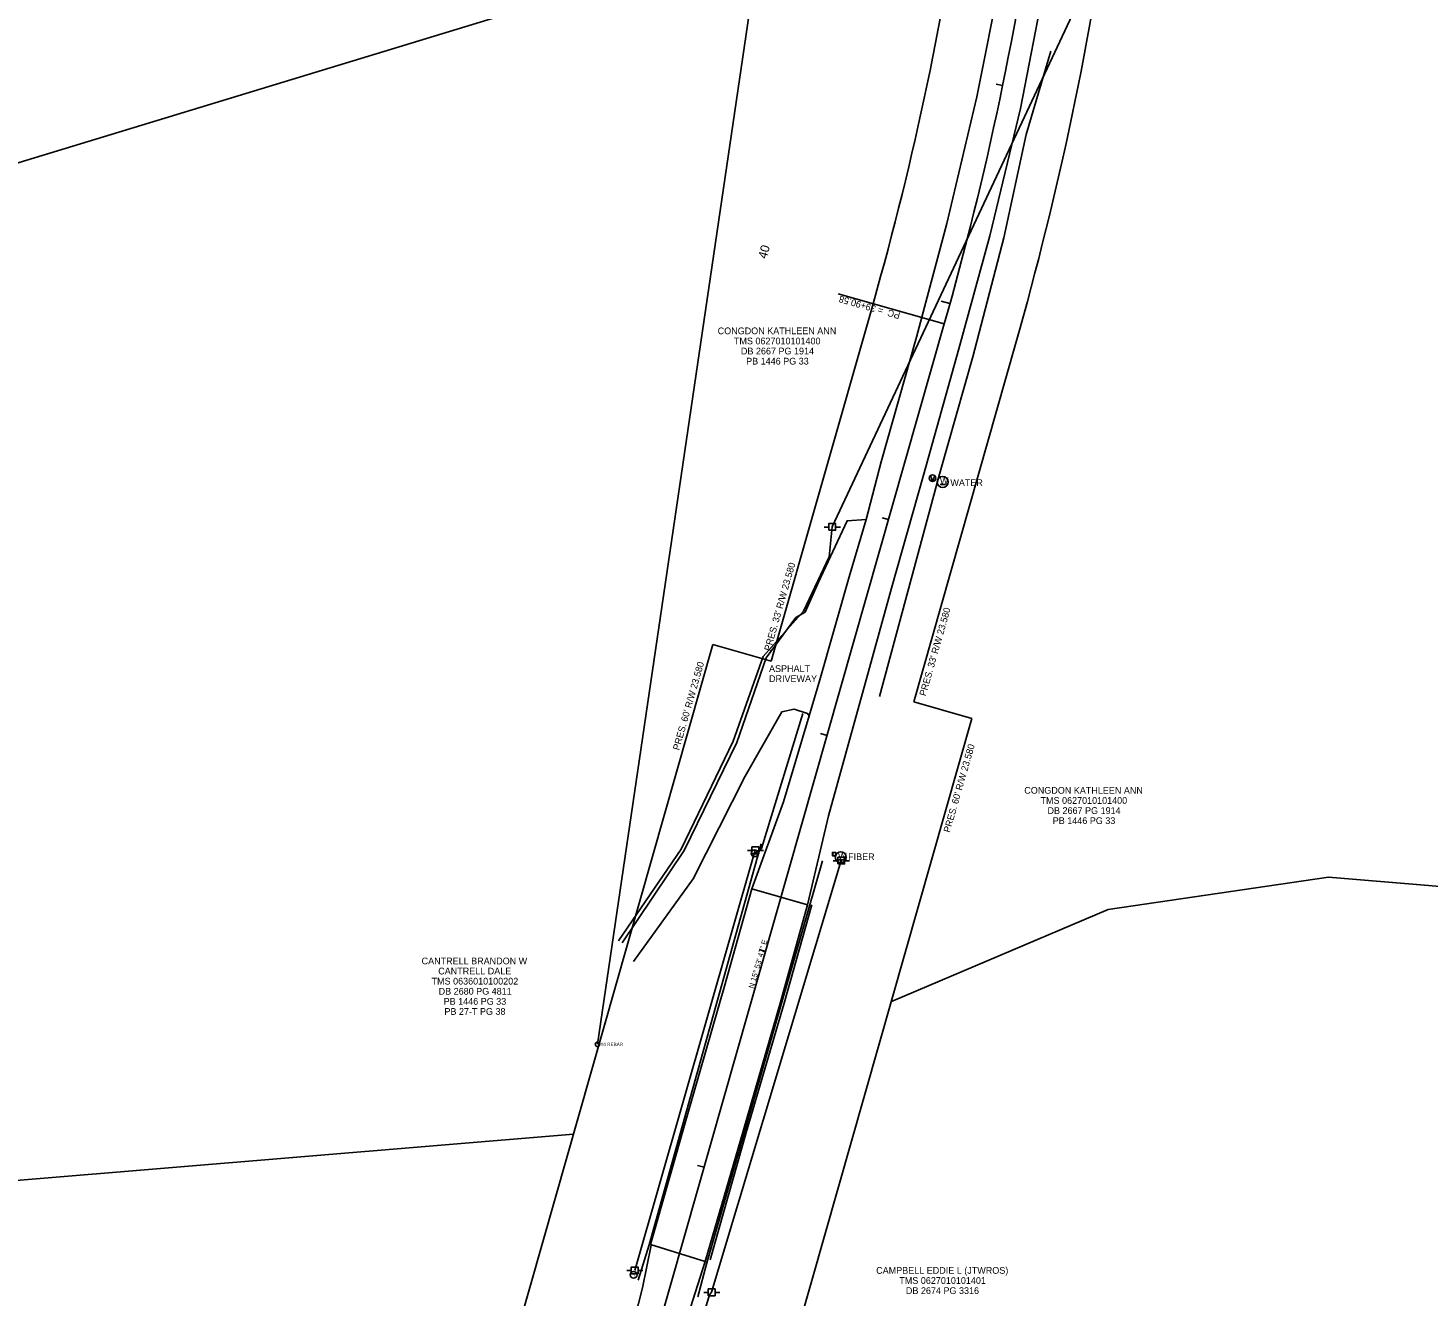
# Model space of a CAD drawing. Extents: x 1618707 to 1620612, y 1189955 to 1192629.
# Drawn here: x 1619365 to 1619988, y 1191545 to 1192110 of the extents above; entities that cross this region are included whole.
import ezdxf

# ---------------------------------------------------------------- set-up
doc = ezdxf.new("R2010")
doc.units = 0
for name, color, linetype in [('RD_EX_Bridge', 7, 'Continuous'), ('RD_EX_DV_Prop', 7, 'Continuous'), ('RD_EX_DV_Prop_txCode', 7, 'Continuous'), ('RD_EX_DV_PropPin', 7, 'Continuous'), ('RD_EX_DV_TX_Prop', 7, 'Continuous'), ('RD_EX_GuardRail', 7, 'Continuous'), ('RD_EX_Road', 7, 'Continuous'), ('RD_EX_RW', 7, 'Continuous'), ('RD_EX_RW_TX', 7, 'Continuous'), ('RD_EX_SU_Elec', 7, 'Continuous'), ('RD_EX_SU_H2O', 7, 'Continuous'), ('RD_EX_SU_Telecom', 7, 'Continuous'), ('RD_EX_UT', 7, 'Continuous'), ('RD_HC_Cl', 7, 'Continuous'), ('RD_HC_Data', 7, 'Continuous'), ('RD_HC_Data_Tic', 7, 'Continuous'), ('RD_HC_TX_Sta20', 7, 'Continuous'), ('RD_TX_Misc1', 7, 'Continuous'), ('RD_TX_Utilities', 7, 'Continuous')]:
    doc.layers.add(name, color=color, linetype=linetype)

msp = doc.modelspace()

# ---------------------------------------------------------------- linework, layer by layer
at = {"layer": 'RD_EX_Bridge'}
for p, q in [((1619687.27, 1191726.81), (1619712.05, 1191719.7)), ((1619642.01, 1191568.35), (1619666.44, 1191560.82))]:
    msp.add_line(p, q, dxfattribs=at)
for points in [[(1619642.01, 1191568.35), (1619658.44, 1191625.81), (1619675.09, 1191683.51), (1619687.27, 1191726.81)], [(1619712.05, 1191719.7), (1619700.01, 1191676.35), (1619683.36, 1191618.91), (1619666.44, 1191560.82)]]:
    msp.add_lwpolyline(points, dxfattribs=at)
at = {"layer": 'RD_EX_DV_Prop'}
msp.add_line((1619618.45, 1191657.59), (1619618.45, 1191657.59), dxfattribs=at)
for points in [[(1618953.32, 1191926.47), (1619691.12, 1192151), (1619618.45, 1191657.59)], [(1619607.74, 1191617.5), (1618753.75, 1191546.6), (1618953.32, 1191926.47)], [(1619749.37, 1191676.7), (1619845.88, 1191717.62), (1619944.11, 1191732.1), (1620034.84, 1191724.45), (1620137.43, 1191712.54), (1620167.24, 1191672.69), (1620224.99, 1191624.67), (1620263.26, 1191557.46), (1620264.11, 1191498.18), (1620236.82, 1191456.97), (1620148.22, 1191262), (1620062.16, 1191160)]]:
    msp.add_lwpolyline(points, dxfattribs=at)
at = {"layer": 'RD_EX_DV_PropPin'}
msp.add_circle((1619618.45, 1191657.59), 1, dxfattribs=at)
at = {"layer": 'RD_EX_GuardRail'}
for points in [[(1619691.4, 1191746.9), (1619641.43, 1191568.28), (1619636.51, 1191552.47)], [(1619718.72, 1191739.37), (1619667.14, 1191560.27), (1619663.21, 1191545.15)]]:
    msp.add_lwpolyline(points, dxfattribs=at)
at = {"layer": 'RD_EX_Road'}
for points in [[(1619818.78, 1192386.23), (1619818.01, 1192332.67), (1619815.33, 1192280.25), (1619810.62, 1192225.96), (1619804.57, 1192175.23), (1619797.92, 1192132.69), (1619787.4, 1192079.58), (1619774.13, 1192023.21), (1619760.61, 1191972.59), (1619744.83, 1191917.11), (1619738.12, 1191891.42), (1619730.55, 1191865.86), (1619717.53, 1191819.93), (1619712.78, 1191803.93), (1619701.26, 1191765.6), (1619687.27, 1191726.81)], [(1619838.66, 1192386.16), (1619838.03, 1192331.37), (1619835.13, 1192278.82), (1619830.44, 1192223.56), (1619824.24, 1192172.25), (1619817.51, 1192128.89), (1619806.84, 1192074.51), (1619793.17, 1192017.72), (1619779.48, 1191967.35), (1619763.64, 1191911.17), (1619749.44, 1191860.79), (1619736.49, 1191814), (1619721.43, 1191759.35), (1619712.05, 1191719.7)], [(1619738.12, 1191891.42), (1619729.62, 1191890.78), (1619716.92, 1191863.52), (1619710.99, 1191850.09), (1619706.87, 1191847.66), (1619693.65, 1191829.74), (1619680.56, 1191792.05), (1619657.08, 1191743.95), (1619629.49, 1191702.73)], [(1619634.44, 1191694.48), (1619661.12, 1191731.24), (1619684.17, 1191777.02), (1619700.64, 1191805.75), (1619706.09, 1191806.81), (1619712.02, 1191804.89), (1619712.78, 1191803.93)], [(1619642.43, 1191568.08), (1619638.48, 1191549.06), (1619626.5, 1191502.03), (1619610.31, 1191444.44), (1619596.77, 1191395.56), (1619582.42, 1191345.02), (1619568.38, 1191294.44), (1619554.25, 1191242.83), (1619539.08, 1191183.69), (1619525.7, 1191133.06), (1619512.41, 1191081.45), (1619499.3, 1191029.35), (1619486.66, 1190976.67)], [(1619666.44, 1191560.82), (1619645.74, 1191496.06), (1619629.32, 1191438.84), (1619615.59, 1191389.97), (1619601.08, 1191338.73), (1619587.7, 1191288.59), (1619573.66, 1191236.16), (1619558.66, 1191179.12), (1619545.49, 1191128.07), (1619532.02, 1191076.56), (1619518.85, 1191024.15), (1619506.08, 1190971.55)]]:
    msp.add_lwpolyline(points, dxfattribs=at)
at = {"layer": 'RD_EX_RW'}
for p, q in [((1619695.83, 1191828.25), (1619741.19, 1191987.5)), ((1619759.31, 1191810.17), (1619804.66, 1191969.42)), ((1619552.55, 1191423.72), (1619669.87, 1191835.65)), ((1619669.87, 1191835.65), (1619695.83, 1191828.25)), ((1619785.28, 1191802.78), (1619759.31, 1191810.17)), ((1619667.96, 1191390.85), (1619785.28, 1191802.78))]:
    msp.add_line(p, q, dxfattribs=at)
for radius in [1493.94, 1427.94]:
    msp.add_arc((1618367.86, 1192378.61), radius, 344.10357, 0.2547, dxfattribs=at)
at = {"layer": 'RD_EX_SU_Elec'}
msp.add_lwpolyline([(1619723.01, 1191888.05), (1619721.59, 1191874.7), (1619710.29, 1191850.53), (1619692.32, 1191830.36), (1619678.95, 1191792.61), (1619655.75, 1191744.47), (1619627.76, 1191703.66)], dxfattribs=at)
at = {"layer": 'RD_EX_SU_H2O'}
msp.add_lwpolyline([(1619713.91, 1191719.73), (1619701.55, 1191675.85), (1619684.7, 1191618.24), (1619668.7, 1191561.55)], dxfattribs=at)
at = {"layer": 'RD_EX_SU_Telecom'}
msp.add_line((1619809.49, 1192062.93), (1619820.36, 1192100.03), dxfattribs=at)
for points in [[(1619744.14, 1191812.54), (1619770.83, 1191911.63), (1619785.66, 1191963.79), (1619799.47, 1192016.76), (1619809.49, 1192062.93)], [(1619709.95, 1191804.93), (1619691.53, 1191744.86), (1619688.46, 1191742.66)], [(1619669.31, 1191547.12), (1619668.4, 1191546.05), (1619652.22, 1191492.17), (1619633.62, 1191435.33), (1619620.26, 1191387.53), (1619605.32, 1191335.94), (1619592.44, 1191286.44), (1619577.21, 1191230.52), (1619562.58, 1191178.36), (1619549.6, 1191128.37)]]:
    msp.add_lwpolyline(points, dxfattribs=at)
at = {"layer": 'RD_EX_UT'}
for p, q in [((1619767.72, 1191908.29), (1619766.74, 1191910.91)), ((1619767.72, 1191908.29), (1619768.71, 1191910.88)), ((1619771.16, 1191906.97), (1619773.48, 1191906.97)), ((1619719.45, 1191888.01), (1619721.51, 1191888.01)), ((1619723.01, 1191888.05), (1619723.01, 1191888.05)), ((1619724.51, 1191888.01), (1619726.65, 1191888.01)), ((1619635.03, 1191556.87), (1619688.77, 1191744)), ((1619685.21, 1191743.96), (1619687.27, 1191743.96)), ((1619688.77, 1191744), (1619688.77, 1191744)), ((1619690.27, 1191743.96), (1619692.41, 1191743.96)), ((1619727.06, 1191739.42), (1619669.31, 1191547.12)), ((1619723.5, 1191739.39), (1619725.56, 1191739.39)), ((1619725.79, 1191739.83), (1619728.1, 1191739.83)), ((1619727.06, 1191739.42), (1619727.06, 1191739.42)), ((1619728.56, 1191739.39), (1619730.7, 1191739.39)), ((1619631.47, 1191556.83), (1619633.53, 1191556.83)), ((1619635.03, 1191556.87), (1619635.03, 1191556.87)), ((1619636.53, 1191556.83), (1619638.67, 1191556.83)), ((1619665.76, 1191547.08), (1619667.81, 1191547.08)), ((1619669.31, 1191547.12), (1619669.31, 1191547.12)), ((1619670.81, 1191547.08), (1619672.95, 1191547.08))]:
    msp.add_line(p, q, dxfattribs=at)
msp.add_lwpolyline([(1619856.04, 1192387.51), (1619834.58, 1192125.99), (1619723.01, 1191888.05)], dxfattribs=at)
for points in [[(1619721.51, 1191886.55), (1619721.51, 1191889.55), (1619724.51, 1191889.55), (1619724.51, 1191886.55)], [(1619687.27, 1191742.5), (1619687.27, 1191745.5), (1619690.27, 1191745.5), (1619690.27, 1191742.5)], [(1619724.6, 1191741.55), (1619723.1, 1191741.55), (1619723.1, 1191743.05), (1619724.6, 1191743.05)], [(1619725.56, 1191737.92), (1619725.56, 1191740.92), (1619728.56, 1191740.92), (1619728.56, 1191737.92)], [(1619633.53, 1191555.37), (1619633.53, 1191558.37), (1619636.53, 1191558.37), (1619636.53, 1191555.37)], [(1619667.81, 1191545.62), (1619667.81, 1191548.62), (1619670.81, 1191548.62), (1619670.81, 1191545.62)]]:
    msp.add_lwpolyline(points, close=True, dxfattribs=at)
for centre, radius in [((1619767.72, 1191909.79), 1.5), ((1619772.23, 1191908.08), 2.45), ((1619688.46, 1191742.66), 1.5), ((1619726.85, 1191740.93), 2.45), ((1619634.56, 1191554.91), 1.5)]:
    msp.add_circle(centre, radius, dxfattribs=at)
at = {"layer": 'RD_HC_Cl'}
msp.add_line((1619610.26, 1191407.28), (1619772.92, 1191978.46), dxfattribs=at)
msp.add_arc((1618367.86, 1192378.61), 1460.94, 344.10357, 0.2547, dxfattribs=at)
at = {"layer": 'RD_HC_Data'}
msp.add_line((1619772.92, 1191978.46), (1619725.65, 1191991.92), dxfattribs=at)
at = {"layer": 'RD_HC_Data_Tic'}
for p, q in [((1619798.93, 1192084.72), (1619795.99, 1192085.32)), ((1619775.47, 1191987.53), (1619771.62, 1191988.6)), ((1619748.11, 1191891.34), (1619745.23, 1191892.16)), ((1619720.72, 1191795.17), (1619717.84, 1191795.99)), ((1619693.33, 1191698.99), (1619690.45, 1191699.81)), ((1619665.94, 1191602.82), (1619663.06, 1191603.64))]:
    msp.add_line(p, q, dxfattribs=at)

# ---------------------------------------------------------------- texts
at = {"layer": 'RD_EX_DV_Prop_txCode'}
msp.add_text('#4 REBAR', height=1.5, dxfattribs=at).set_placement((1619619.87, 1191656.78))
at = {"layer": 'RD_EX_DV_TX_Prop'}
for s, p in [('CONGDON KATHLEEN ANN', (1619672, 1191973.89)), ('TMS 0627010101400', (1619679.23, 1191969.39)), ('DB 2667 PG 1914', (1619682.35, 1191964.89)), ('PB 1446 PG 33', (1619684.67, 1191960.39)), ('CONGDON KATHLEEN ANN', (1619808.58, 1191769.21)), ('TMS 0627010101400', (1619815.82, 1191764.71)), ('DB 2667 PG 1914', (1619818.93, 1191760.21)), ('PB 1446 PG 33', (1619821.26, 1191755.71)), ('CANTRELL BRANDON W', (1619540.11, 1191693.22)), ('TMS 0636010100202', (1619544.54, 1191684.22)), ('CANTRELL DALE', (1619547.5, 1191688.72)), ('DB 2680 PG 4811', (1619547.69, 1191679.72)), ('PB 1446 PG 33', (1619549.93, 1191675.22)), ('PB 27-T PG 38', (1619550.27, 1191670.72)), ('CAMPBELL EDDIE L (JTWROS)', (1619742.61, 1191555.38)), ('TMS 0627010101401', (1619752.91, 1191550.88)), ('DB 2674 PG 3316', (1619755.85, 1191546.38))]:
    msp.add_text(s, height=3, dxfattribs=at).set_placement(p)
at = {"layer": 'RD_EX_RW_TX'}
for s, p in [("PRES. 33' R/W 23.580", (1619695.51, 1191832.57)), ("PRES. 33' R/W 23.580", (1619764.65, 1191812.51)), ("PRES. 60' R/W 23.580", (1619654.84, 1191788.37)), ("PRES. 60' R/W 23.580", (1619775.41, 1191751.71))]:
    msp.add_text(s, height=3, rotation=74.10357, dxfattribs=at).set_placement(p)
at = {"layer": 'RD_EX_UT'}
for p in [(1619771, 1191907.08), (1619725.62, 1191739.93)]:
    msp.add_text('W', height=3, dxfattribs=at).set_placement(p)
for s, height, p in [('T', 1.5, (1619688.11, 1191741.84)), ('E', 1, (1619723.38, 1191741.82)), ('T', 1.5, (1619634.21, 1191554.09))]:
    msp.add_text(s, height=height, rotation=360, dxfattribs=at).set_placement(p)
at = {"layer": 'RD_HC_Data'}
for s, height, rotation, p in [('PC  = 39+90.58', 3, 164.10357, (1619753.55, 1191983.46)), ('N 15%%d 53\' 47" E', 2.4, 74.10357, (1619688.04, 1191682.24))]:
    msp.add_text(s, height=height, rotation=rotation, dxfattribs=at).set_placement(p)
at = {"layer": 'RD_HC_TX_Sta20'}
msp.add_text('40', height=4, rotation=74.47301, dxfattribs=at).set_placement((1619693.76, 1192007.22))
at = {"layer": 'RD_TX_Misc1'}
for s, p in [('ASPHALT', (1619694.87, 1191823.46)), ('DRIVEWAY', (1619694.87, 1191818.96))]:
    msp.add_text(s, height=3, dxfattribs=at).set_placement(p)
at = {"layer": 'RD_TX_Utilities'}
for s, p in [('WATER', (1619775.65, 1191906.26)), ('FIBER', (1619730.11, 1191739.63))]:
    msp.add_text(s, height=3, dxfattribs=at).set_placement(p)

doc.saveas('drawing.dxf')
